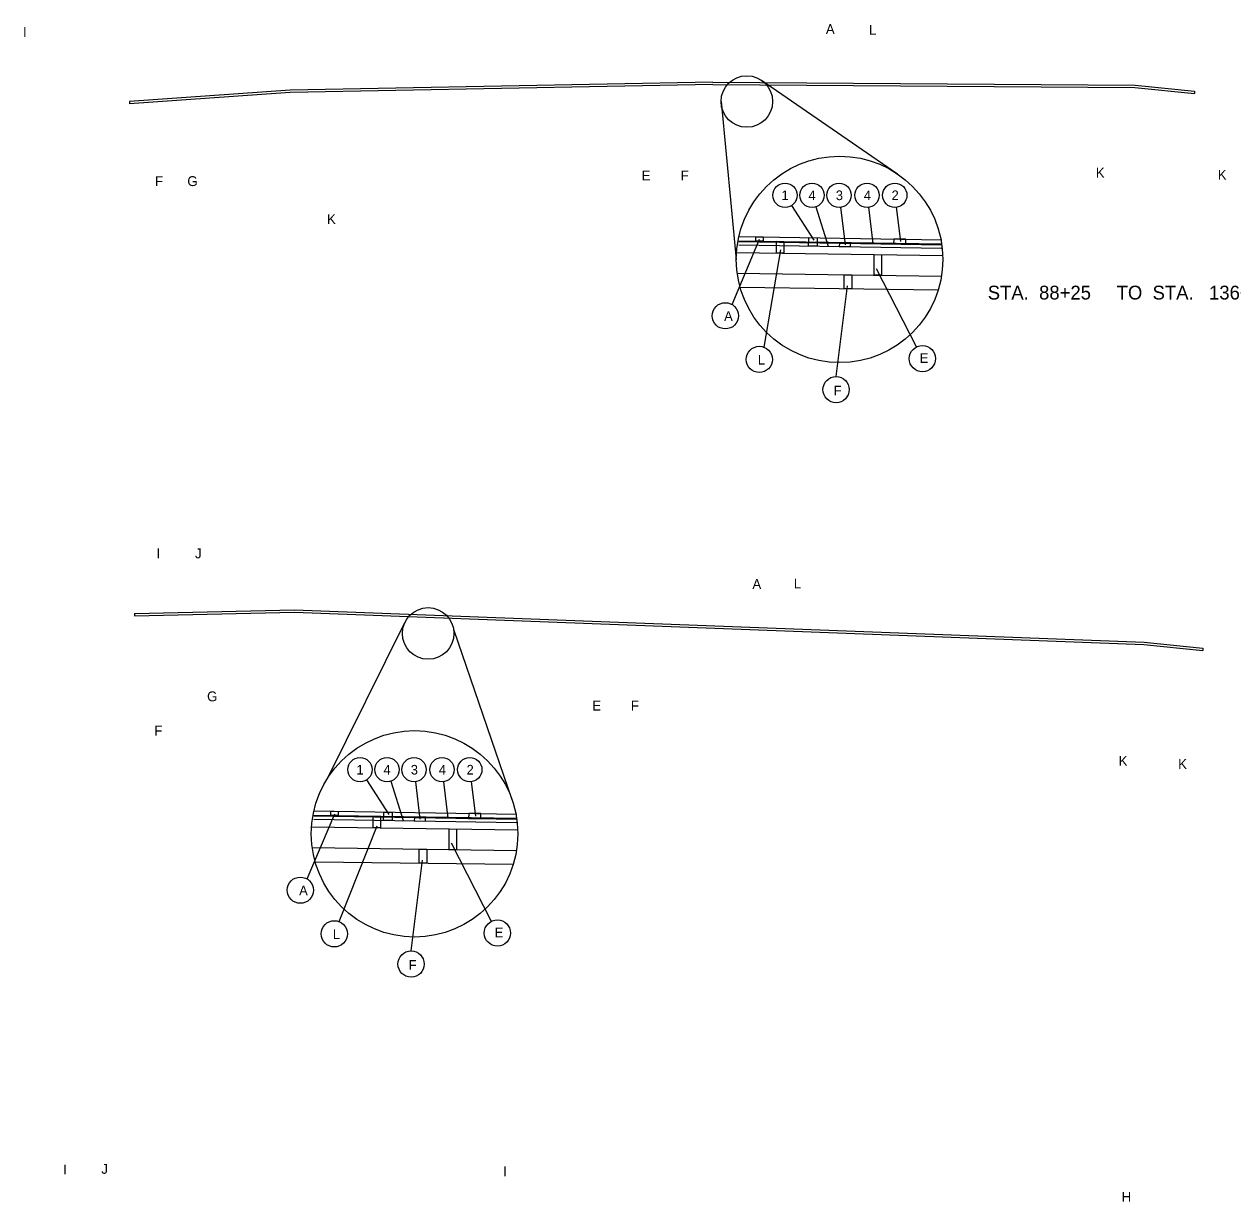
# Model space of a CAD drawing. Extents: x -210 to 558, y -150 to 205.
# Drawn here: x -210.2 to -141.5, y 66.6 to 133.5 of the extents above; entities that cross this region are included whole.
import ezdxf

# ---------------------------------------------------------------- set-up
doc = ezdxf.new("R2010")
doc.units = 0
for name, color, linetype in [('Level 1', 7, 'Continuous'), ('Level 3', 7, 'Continuous'), ('Level 59', 7, 'Continuous')]:
    doc.layers.add(name, color=color, linetype=linetype)

msp = doc.modelspace()

# ---------------------------------------------------------------- linework, layer by layer
at = {"layer": 'Level 1'}
for p, q in [((-171.03, 130.224), (-195.054, 129.774)), ((-171.03, 130.089), (-195.048, 129.639)), ((-171.03, 130.224), (-147.028, 130.06)), ((-171.03, 130.089), (-147.035, 129.925)), ((-168.26, 130.33), (-160.522, 125.011)), ((-147.035, 129.925), (-143.646, 129.579)), ((-147.028, 130.06), (-143.646, 129.715)), ((-195.054, 129.774), (-204.189, 129.134)), ((-195.048, 129.639), (-204.189, 128.999)), ((-143.646, 129.715), (-143.646, 129.579)), ((-204.189, 129.134), (-204.189, 128.999)), ((-170.561, 129.124), (-169.691, 120.147)), ((-166.551, 123.213), (-165.289, 121.244)), ((-165.179, 123.137), (-164.465, 120.896)), ((-163.772, 123.109), (-163.514, 120.983)), ((-162.178, 123.109), (-161.927, 121.043)), ((-160.601, 123.109), (-160.364, 121.158)), ((-169.935, 117.586), (-168.365, 121.3)), ((-169.594, 121.212), (-158.02, 121.028)), ((-169.553, 120.977), (-158.024, 120.793)), ((-169.55, 121.165), (-158.021, 120.981)), ((-169.545, 121.447), (-158.017, 121.264)), ((-169.545, 121.447), (-158.017, 121.264)), ((-169.678, 120.538), (-157.958, 120.369)), ((-168.108, 115.153), (-167.156, 120.692)), ((-159.453, 115.17), (-161.724, 119.613)), ((-169.639, 119.364), (-158.032, 119.192)), ((-169.473, 118.561), (-158.216, 118.413)), ((-164.02, 113.487), (-163.367, 118.65)), ((-203.89, 100.014), (-194.81, 100.22)), ((-203.89, 99.879), (-194.811, 100.085)), ((-203.89, 100.014), (-203.89, 99.879)), ((-194.811, 100.085), (-146.526, 98.253)), ((-194.81, 100.22), (-146.517, 98.388)), ((-188.545, 99.484), (-192.974, 90.571)), ((-185.752, 99.064), (-182.444, 89.438)), ((-146.526, 98.253), (-143.181, 97.905)), ((-146.517, 98.388), (-143.181, 98.04)), ((-143.181, 98.04), (-143.181, 97.905)), ((-190.708, 90.556), (-189.446, 88.586)), ((-189.337, 90.479), (-188.622, 88.238)), ((-187.929, 90.452), (-187.671, 88.325)), ((-186.335, 90.452), (-186.084, 88.386)), ((-184.758, 90.452), (-184.522, 88.501)), ((-193.703, 88.789), (-182.174, 88.606)), ((-193.703, 88.789), (-182.174, 88.606)), ((-194.092, 84.928), (-192.505, 88.619)), ((-193.751, 88.555), (-182.178, 88.371)), ((-193.751, 88.555), (-182.178, 88.371)), ((-193.71, 88.319), (-182.181, 88.136)), ((-193.707, 88.507), (-182.178, 88.324)), ((-192.266, 82.496), (-190.103, 87.939)), ((-193.835, 87.88), (-182.115, 87.712)), ((-193.796, 86.707), (-182.189, 86.534)), ((-183.611, 82.512), (-185.881, 86.956)), ((-193.63, 85.903), (-182.373, 85.755)), ((-188.177, 80.83), (-187.524, 85.992))]:
    msp.add_line(p, q, dxfattribs=at)
for points in [[(-168.588, 121.431), (-168.169, 121.425), (-168.169, 121.19), (-168.588, 121.197)], [(-167.414, 121.178), (-166.994, 121.171), (-166.994, 120.502), (-167.414, 120.509)], [(-165.575, 121.384), (-165.087, 121.376), (-165.094, 120.906), (-165.582, 120.913)], [(-163.838, 120.886), (-163.2, 120.876), (-163.197, 121.064), (-163.835, 121.074)], [(-160.752, 121.025), (-160.057, 121.014), (-160.052, 121.296), (-160.747, 121.307)], [(-161.855, 120.424), (-161.435, 120.417), (-161.438, 119.244), (-161.858, 119.251)], [(-163.552, 119.276), (-163.132, 119.269), (-163.134, 118.474), (-163.554, 118.481)], [(-192.745, 88.774), (-192.326, 88.767), (-192.326, 88.532), (-192.745, 88.539)], [(-189.732, 88.726), (-189.244, 88.718), (-189.252, 88.248), (-189.74, 88.256)], [(-184.909, 88.367), (-184.214, 88.356), (-184.209, 88.638), (-184.904, 88.65)], [(-190.338, 88.502), (-189.919, 88.495), (-189.919, 87.826), (-190.338, 87.833)], [(-187.995, 88.228), (-187.357, 88.218), (-187.354, 88.406), (-187.992, 88.416)], [(-186.012, 87.767), (-185.592, 87.76), (-185.595, 86.587), (-186.015, 86.594)], [(-187.709, 86.619), (-187.29, 86.612), (-187.291, 85.817), (-187.711, 85.824)]]:
    msp.add_lwpolyline(points, close=True, dxfattribs=at)
for centre, radius in [((-169.093, 129.124), 1.467), ((-163.823, 120.147), 5.869), ((-166.924, 123.795), 0.691), ((-165.389, 123.795), 0.691), ((-163.855, 123.795), 0.691), ((-162.261, 123.795), 0.691), ((-160.684, 123.795), 0.691), ((-170.316, 116.942), 0.746), ((-168.384, 114.46), 0.746), ((-159.114, 114.506), 0.746), ((-164.02, 112.742), 0.746), ((-187.208, 98.881), 1.467), ((-187.98, 87.49), 5.869), ((-187.98, 87.49), 5.869), ((-191.081, 91.138), 0.691), ((-189.546, 91.138), 0.691), ((-188.012, 91.138), 0.691), ((-186.418, 91.138), 0.691), ((-184.842, 91.138), 0.691), ((-194.473, 84.284), 0.746), ((-192.541, 81.803), 0.746), ((-183.271, 81.848), 0.746), ((-188.177, 80.084), 0.746)]:
    msp.add_circle(centre, radius, dxfattribs=at)

# ---------------------------------------------------------------- texts
for s, p in [('1', (-167.124, 123.518)), ('4', (-165.59, 123.518)), ('3', (-164.036, 123.518)), ('4', (-162.442, 123.518)), ('2', (-160.866, 123.518)), ('1', (-191.282, 90.86)), ('4', (-189.747, 90.86)), ('3', (-188.193, 90.86)), ('4', (-186.6, 90.86)), ('2', (-185.023, 90.86))]:
    msp.add_text(s, height=0.547, dxfattribs=at).set_placement(p)
at = {"layer": 'Level 3'}
for s, p in [('I', (-210.239, 132.798)), ('A', (-164.602, 132.961)), ('L', (-162.153, 132.916)), ('E', (-175.076, 124.635)), ('F', (-172.857, 124.635)), ('K', (-149.26, 124.796)), ('K', (-142.327, 124.677)), ('F', (-202.736, 124.317)), ('G', (-200.895, 124.317)), ('K', (-192.954, 122.157)), ('I', (-202.65, 103.154)), ('J', (-200.458, 103.154)), ('A', (-168.777, 101.408)), ('L', (-166.427, 101.443)), ('G', (-199.773, 95.023)), ('E', (-177.881, 94.497)), ('F', (-175.689, 94.497)), ('F', (-202.769, 93.074)), ('K', (-147.956, 91.355)), ('K', (-144.579, 91.177)), ('J', (-205.782, 68.16)), ('I', (-207.96, 68.121)), ('I', (-182.945, 68.02)), ('H', (-147.788, 66.566))]:
    msp.add_text(s, height=0.562, dxfattribs=at).set_placement(p)
at = {"layer": 'Level 59'}
for s, height, p in [('STA.  88+25     TO  STA.   136+50', 0.78544, (-155.401, 117.868)), ('A', 0.547, (-170.383, 116.653)), ('E', 0.547, (-159.264, 114.265)), ('L', 0.547, (-168.467, 114.171)), ('F', 0.547, (-164.158, 112.416)), ('A', 0.547, (-194.54, 83.996)), ('L', 0.547, (-192.625, 81.513)), ('E', 0.547, (-183.421, 81.608)), ('F', 0.547, (-188.315, 79.759))]:
    msp.add_text(s, height=height, dxfattribs=at).set_placement(p)

doc.saveas('drawing.dxf')
